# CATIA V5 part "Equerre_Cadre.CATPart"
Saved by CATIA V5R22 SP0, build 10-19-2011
Part number: Equerre_Cadre
Bounding box of the stored display mesh (mm): x -10 to 10, y -10 to 10, z 0 to 20
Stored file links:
  U:\S9A\PER\CAO\Assemblage\Cadre\Cadre_Metalique\Equerre_Cadre.CATPart
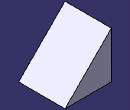
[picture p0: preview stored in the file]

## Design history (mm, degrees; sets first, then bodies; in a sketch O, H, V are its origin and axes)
Body1 (main body)
  Sketch1 on xy-plane, origin (0, 0, 0), H (1, 0, 0), V (0, 1, 0)
    point P1 (-10, 10)
    line L1 (-10, 10) -> (10, 10)
    line L2 (10, 10) -> (10, -10)
    line L3 (10, -10) -> (-10, -10)
    line L4 (-10, -10) -> (-10, 10)
    point P2 (10, 10)
    point P3 (10, -10)
    point P4 (-10, -10)
    length L4 = 20
    length L1 = 20
    horizontal: L1 H, L3 H
    vertical: L2 V, L4 V
    equidistance: P1 P3 O, P4 P2 O
  Pad1: profile Sketch1, direction (0, 0, 1), length 20
  Sketch2 on face of Pad1 from Sketch1.L3, origin (0, -10, 0), H (1, 0, 0), V (0, 0, 1)
    point P1 (10, 0)
    point P2 (10, 20)
    line L1 (10, 20) -> (10, 0)
    line L2 (-10, 20) -> (10, 20)
    point P3 (-10, 20)
    point P4 (10, 20)
    line L3 (-10, 20) -> (10, 0)
    point P5 (-10, 20)
    point P6 (10, 0)
    reference projected point E1 (10, 0) from vertex [face of Pad1 from Sketch1.L2 | start face of Pad1 | face of Pad1 from Sketch1.L3]
    reference projected point E2 (-10, 20) from vertex [face of Pad1 from Sketch1.L3 | end face of Pad1 | face of Pad1 from Sketch1.L4]
    reference projected point E3 (10, 20) from vertex [face of Pad1 from Sketch1.L2 | end face of Pad1 | face of Pad1 from Sketch1.L3]
    coincidence: P1 H, P6 P1, P5 P3, P1 E1, P3 E2, P2 E3, P4 P2
  Pocket1: profile Sketch2, direction (0, 1, 0), through (limit type 3)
